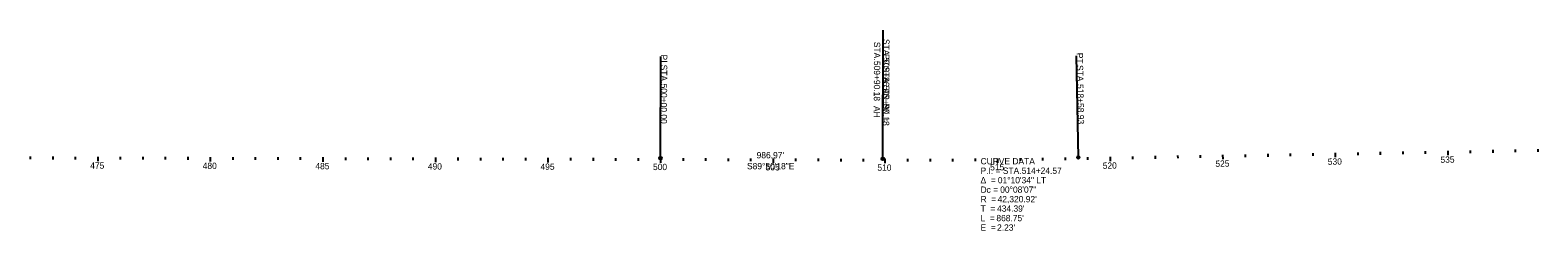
# Model space of a CAD drawing. Extents: x 117326 to 225548, y 573011 to 581051.
# Drawn here: x 164665 to 171362, y 577158 to 578047 of the extents above; entities that cross this region are included whole.
import ezdxf

# ---------------------------------------------------------------- set-up
doc = ezdxf.new("R2010")
doc.units = 0
for name, color, linetype in [('_CIVIL_CONSTRUCTION', 7, 'Continuous'), ('GE_P_Alignment', 7, 'Continuous'), ('GE_P_Alignment_100_Bearings', 7, 'Continuous'), ('GE_P_Alignment_100_Cardinal_Points', 7, 'Continuous'), ('GE_P_Alignment_100_Curve_Data', 7, 'Continuous')]:
    doc.layers.add(name, color=color, linetype=linetype)

msp = doc.modelspace()

# ---------------------------------------------------------------- linework, layer by layer
at = {"layer": 'GE_P_Alignment'}
for p, q in [((168452.3, 577477.2), (168453.9, 578047.2)), ((167465.3, 577480), (167466.6, 577930)), ((168452.3, 577477.2), (168453.5, 577927.2)), ((169321, 577483.6), (169313, 577933.6))]:
    msp.add_line(p, q, dxfattribs=at)
for centre in [(167465.3, 577480), (168452.3, 577477.2), (168452.3, 577477.2), (169321, 577483.6)]:
    msp.add_circle(centre, 6, dxfattribs=at)
at = {"layer": 'GE_P_Alignment_100_Curve_Data'}
for p, q in [((171361.7, 577519.8), (171361.9, 577507.8)), ((164665.3, 577487), (164665.3, 577475)), ((164765.3, 577486.7), (164765.3, 577474.7)), ((164865.3, 577486.5), (164865.3, 577474.5)), ((164965.3, 577486.2), (164965.3, 577466.2)), ((165065.3, 577486), (165065.3, 577474)), ((165165.3, 577485.7), (165165.3, 577473.7)), ((165265.3, 577485.5), (165265.3, 577473.5)), ((165365.3, 577485.2), (165365.3, 577473.2)), ((165465.3, 577485), (165465.3, 577465)), ((165565.3, 577484.7), (165565.3, 577472.7)), ((165665.3, 577484.5), (165665.3, 577472.5)), ((165765.3, 577484.2), (165765.3, 577472.2)), ((165865.3, 577484), (165865.3, 577472)), ((165965.3, 577483.7), (165965.3, 577463.7)), ((166065.3, 577483.5), (166065.3, 577471.5)), ((166165.3, 577483.2), (166165.3, 577471.2)), ((166265.3, 577483), (166265.3, 577471)), ((166365.3, 577482.7), (166365.3, 577470.7)), ((166465.3, 577482.5), (166465.3, 577462.5)), ((166565.3, 577482.2), (166565.3, 577470.2)), ((166665.3, 577482), (166665.3, 577470)), ((166765.3, 577481.7), (166765.3, 577469.7)), ((166865.3, 577481.5), (166865.3, 577469.5)), ((166965.3, 577481.2), (166965.3, 577461.2)), ((167065.3, 577481), (167065.3, 577469)), ((167165.3, 577480.7), (167165.3, 577468.7)), ((167265.3, 577480.5), (167265.3, 577468.5)), ((167365.3, 577480.2), (167365.3, 577468.2)), ((167465.3, 577480), (167465.2, 577460)), ((167565.3, 577479.7), (167565.3, 577467.7)), ((167665.3, 577479.4), (167665.3, 577467.4)), ((167765.3, 577479.1), (167765.3, 577467.1)), ((167865.3, 577478.8), (167865.3, 577466.8)), ((167965.3, 577478.6), (167965.2, 577458.6)), ((168065.3, 577478.3), (168065.3, 577466.3)), ((168165.3, 577478), (168165.3, 577466)), ((168265.3, 577477.7), (168265.3, 577465.7)), ((168365.3, 577477.4), (168365.3, 577465.4)), ((168462.1, 577477.2), (168462, 577457.2)), ((168562.1, 577477), (168562.1, 577465)), ((168662.1, 577477.1), (168662.1, 577465.1)), ((168762.1, 577477.4), (168762.1, 577465.4)), ((168862.1, 577478), (168862.2, 577466)), ((168962.1, 577478.8), (168962.3, 577458.8)), ((169062.1, 577479.9), (169062.2, 577467.9)), ((169162.1, 577481.1), (169162.2, 577469.1)), ((169262, 577482.6), (169262.2, 577470.6)), ((169362, 577484.4), (169362.2, 577472.4)), ((169462, 577486.1), (169462.4, 577466.1)), ((169562, 577487.9), (169562.2, 577475.9)), ((169662, 577489.7), (169662.2, 577477.7)), ((169762, 577491.5), (169762.2, 577479.5)), ((169862, 577493.2), (169862.2, 577481.2)), ((169961.9, 577495), (169962.3, 577475)), ((170061.9, 577496.8), (170062.1, 577484.8)), ((170161.9, 577498.5), (170162.1, 577486.5)), ((170261.9, 577500.3), (170262.1, 577488.3)), ((170361.9, 577502.1), (170362.1, 577490.1)), ((170461.9, 577503.8), (170462.2, 577483.9)), ((170561.8, 577505.6), (170562.1, 577493.6)), ((170661.8, 577507.4), (170662, 577495.4)), ((170761.8, 577509.2), (170762, 577497.2)), ((170861.8, 577510.9), (170862, 577498.9)), ((170961.8, 577512.7), (170962.1, 577492.7)), ((171061.8, 577514.5), (171062, 577502.5)), ((171161.7, 577516.2), (171162, 577504.2)), ((171261.7, 577518), (171261.9, 577506))]:
    msp.add_line(p, q, dxfattribs=at)

# ---------------------------------------------------------------- texts
at = {"layer": '_CIVIL_CONSTRUCTION'}
msp.add_text('S89°50\'18"E', height=28, rotation=359.83842, dxfattribs=at).set_placement((167849.3, 577430.9))
at = {"layer": 'GE_P_Alignment'}
for s, rotation, p in [('STA. ', 269.83842, (168413.2, 577995.7)), ('STA. ', 269.83842, (168454.2, 578008.3)), ('PI', 269.83842, (167467, 577938.9)), ('509+86.96', 269.83842, (168453.9, 577923.8)), ('PC', 269.83833, (168454, 577942)), ('PT', 271.01448, (169313.2, 577946.9)), (' STA. ', 269.83842, (167466.9, 577905)), ('509+90.18', 269.83842, (168413, 577911.2)), (' STA. ', 269.83833, (168453.9, 577896.1)), (' STA. ', 271.01448, (169314, 577902.8)), ('500+00.00', 269.83842, (167466.6, 577810.5)), ('509+90.18', 269.83833, (168453.6, 577801.6)), ('518+58.93', 271.01448, (169315.6, 577808.3)), (' BK =', 269.83842, (168453.4, 577734.2)), (' AH', 269.83842, (168412.4, 577721.6))]:
    msp.add_text(s, height=28, rotation=rotation, dxfattribs=at).set_placement(p)
at = {"layer": 'GE_P_Alignment_100_Bearings'}
for s, p in [('CURVE DATA', (168886.6, 577452.4)), ('Δ  = ', (168886.6, 577368.4)), ('P.I. = STA. ', (168886.6, 577410.4)), ('01°10\'34" LT', (168963.4, 577368.4)), ('514+24.57', (169069.3, 577410.4)), ('Dc = ', (168886.6, 577326.4)), ('00°08\'07"', (168974, 577326.4)), ('T  = ', (168886.6, 577242.4)), ('R  = ', (168886.6, 577284.4)), ("434.39'", (168960, 577242.4)), ("42,320.92'", (168962.4, 577284.4)), ('L  = ', (168886.6, 577200.4)), ('E  = ', (168886.6, 577158.4)), ("868.75'", (168957, 577200.4)), ("2.23'", (168960, 577158.4))]:
    msp.add_text(s, height=28, dxfattribs=at).set_placement(p)
at = {"layer": 'GE_P_Alignment_100_Cardinal_Points'}
msp.add_text("986.97'", height=28, rotation=359.83842, dxfattribs=at).set_placement((167892, 577479.2))
at = {"layer": 'GE_P_Alignment_100_Curve_Data'}
for s, rotation, p in [('475', 359.85657, (164932.1, 577433.3)), ('480', 359.85657, (165431.7, 577432.1)), ('485', 359.85657, (165932.1, 577430.8)), ('490', 359.85657, (166431.7, 577429.6)), ('495', 359.85657, (166932.1, 577428.3)), ('500', 359.83842, (167431.7, 577427.1)), ('505', 359.83842, (167932.1, 577425.6)), ('510', 359.85162, (168428.5, 577424.2)), ('515', 0.52854, (168929.5, 577425.5)), ('520', 1.01448, (169429.5, 577432.6)), ('525', 1.01448, (169929.8, 577441.4)), ('530', 1.01448, (170429.3, 577450.3)), ('535', 1.01448, (170929.7, 577459.1))]:
    msp.add_text(s, height=28, rotation=rotation, dxfattribs=at).set_placement(p)

doc.saveas('drawing.dxf')
